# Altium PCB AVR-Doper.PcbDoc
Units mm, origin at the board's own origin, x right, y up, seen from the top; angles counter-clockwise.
Board outline 152.4 x 101.6 mm, 2 copper layers (Top Layer, Bottom Layer); 39 components, 29 nets, 126 pads, 0 vias.
Unrouted connection lines stored in the file: 5.
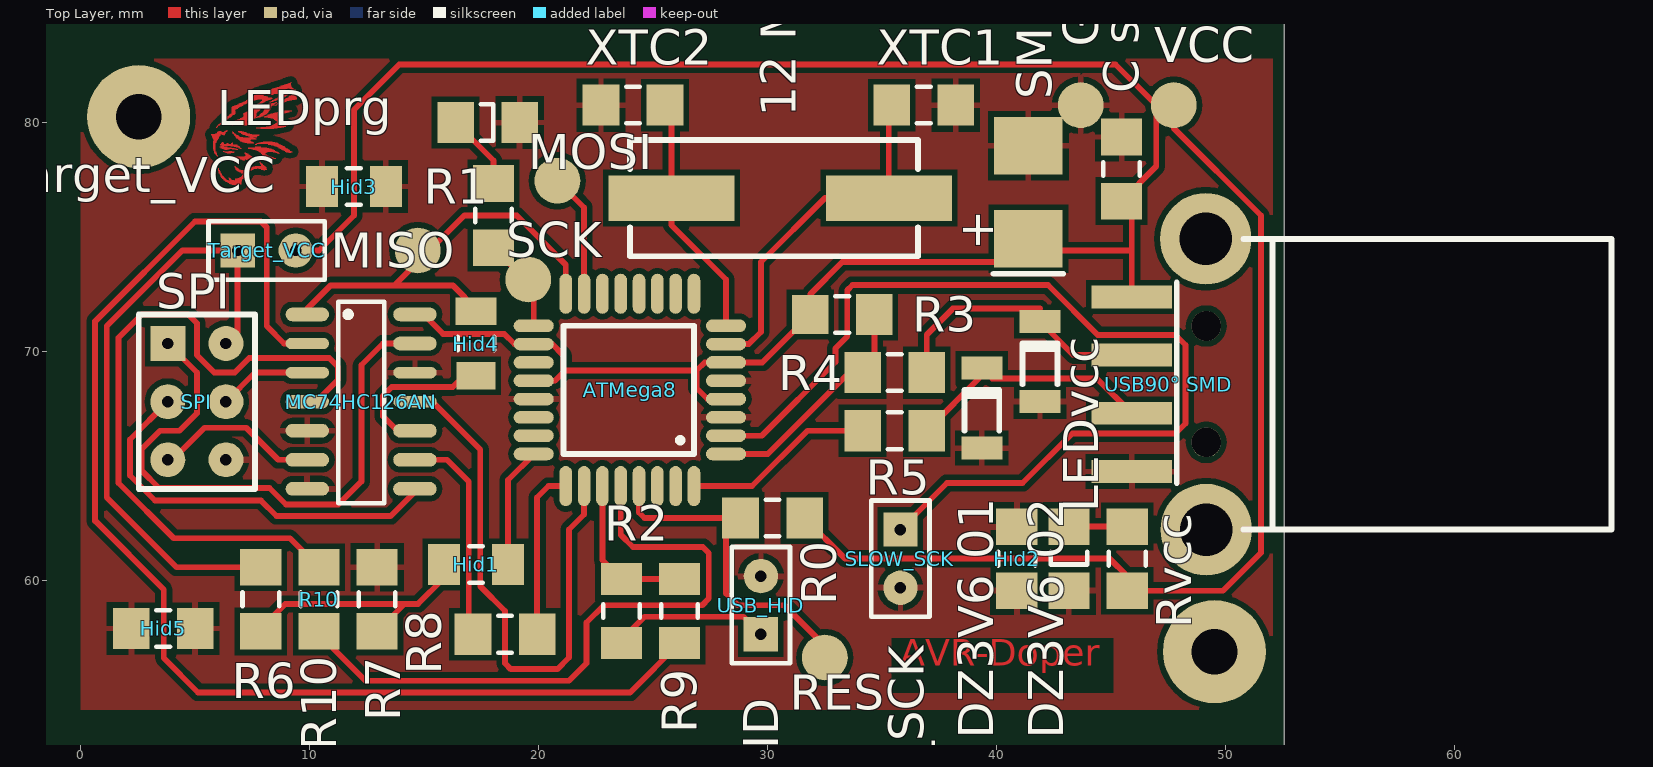
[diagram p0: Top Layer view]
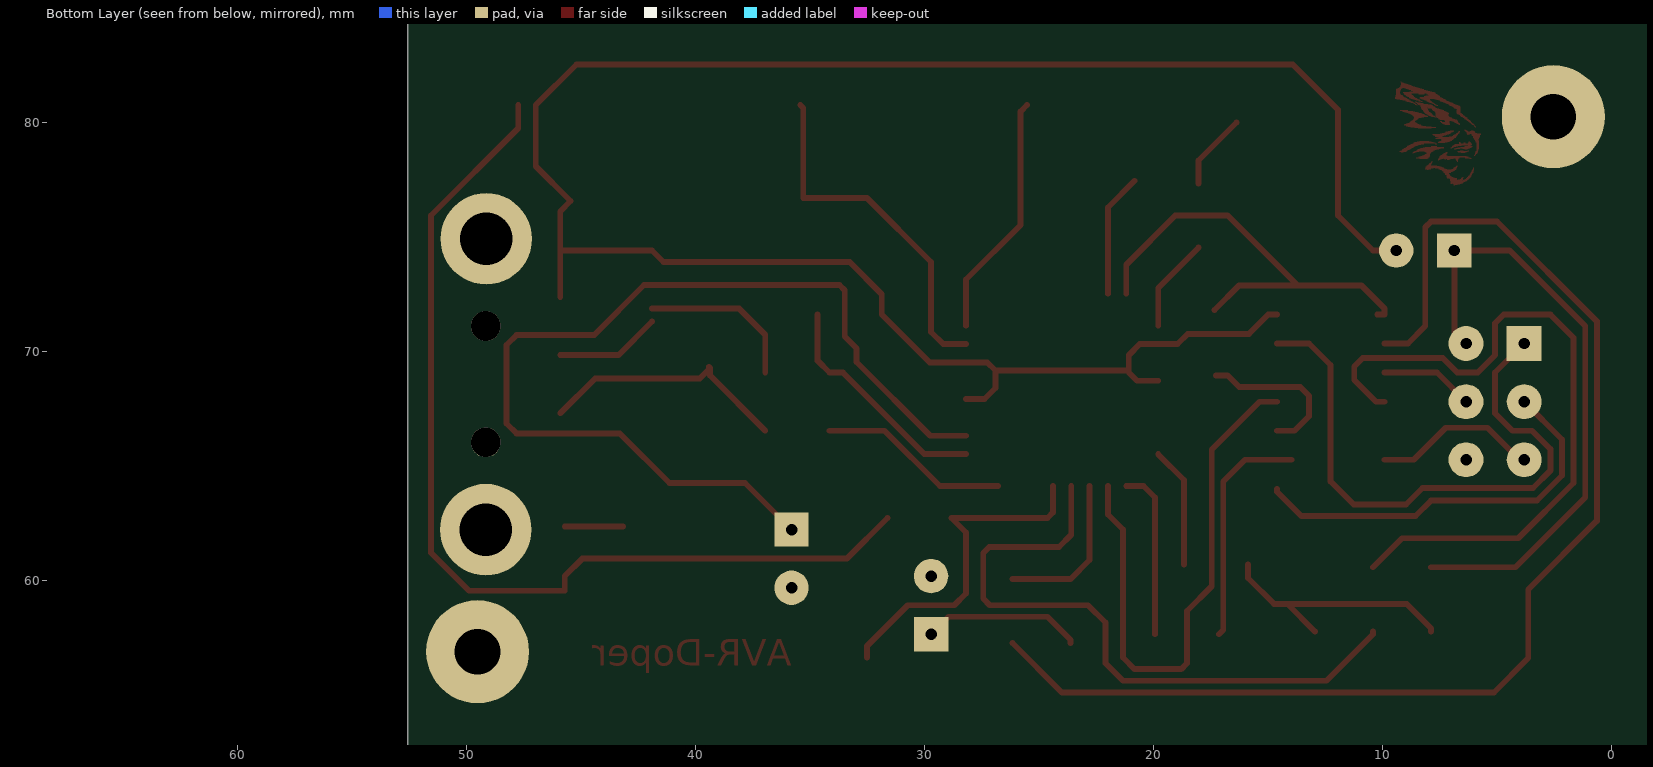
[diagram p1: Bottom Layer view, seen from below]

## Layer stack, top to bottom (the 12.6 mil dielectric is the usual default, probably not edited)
Top Layer: signal copper 0.0356
Dielectric: dielectric 0.32, FR-4, Dk 4.8
Bottom Layer: signal copper 0.0356

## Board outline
-99.822,25.4 52.578,25.4 52.578,127 -99.822,127

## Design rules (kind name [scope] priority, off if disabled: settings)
Clearance [All] p1: gap=0.254
PolygonConnect [All] p1: connectstyle=Relief reliefconductorwidth=0.254 reliefentries=4 polygonreliefangle="90 Angle"
RoutingVias [All] p1: holewidth=0.711 width=1.27 viastyle="Through Hole" minholewidth=0.711 minwidth=1.27 maxholewidth=0.711 maxwidth=1.27
SilkscreenOverComponentPads [All] p1: minsilkscreentomaskgap=0.254
SolderMaskExpansion [All] p1: expansion=0.102
TestPointUsage [All] p1: valid=0 allowmultiple=FALSE
Testpoint [All] p1: side=15 testpointundercomponent=TRUE minsize=1.016 maxsize=2.54 preferedsize=1.524 minholesize=0 maxholesize=1.016 preferedholesize=0.813 testpointgrid=0.025 style=1023 order=0123456789
Width [All] p1: maxlimit=0.254 minlimit=0.254 preferedwidth=0.254
23 further rules are at their usual default settings.

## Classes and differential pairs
component class AVR-Doper: "12 MHZ" ATMega8 "ATmega88 SMD" "C sz1" "DZ3V6 01" "DZ3V6 02" GND LEDprg LEDvcc MC74HC126AN MISO MOSI R0 R1 R2 R3 R4 R5 R6 R7 R8 R9 R10 RES Rvcc SCK SLOW_SCK "SMD 47uF" SPI Target_VCC "USB90° SMD" USB_HID VCC XTC1 XTC2

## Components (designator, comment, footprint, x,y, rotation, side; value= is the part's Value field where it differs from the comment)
"12 MHZ" "12 MHZ" Quartz 35.306,76.708 r180 top (schematic designator "? MHZ")
ATMega8 "ATMega8" ATMega8 28.194,65.532 r180 top
"C sz1" "Cap" "SM 3216[1206]"#1 45.466,77.978 r90 top
"DZ3V6 01" "Diode" DO-80 39.37,65.786 r90 top
"DZ3V6 02" "Diode" DO-80 41.91,67.818 r90 top
GND "Mérőpont" Mérőpont 43.688,80.772 r0 top
Hid1 "Res" "SM 3216[1206]"#2 17.272,60.706 r180 top (schematic designator RRES)
Hid2 "Res" "SM 3216[1206]"#1 40.894,60.96 r270 top (schematic designator RRES)
Hid3 "Res" "SM 3216[1206]"#2 11.938,77.216 r0 top (schematic designator RRES)
Hid4 "Res" "SM 3216[1206]"#3 17.272,70.358 r90 top (schematic designator RRES)
Hid5 "Res" "SM 3216[1206]"#1 3.607,57.912 r0 top (schematic designator RRES)
LEDprg "LED" "SM 3216[1206] - pol" 17.78,80.01 r0 top
LEDvcc "LED" "SM 3216[1206] - pol" 43.18,60.96 r270 top
MC74HC126AN "SMD 14 láb" "SMD 14 láb" 9.906,71.628 r0 top
MISO "Mérőpont" Mérőpont 14.732,74.422 r90 top
MOSI "Mérőpont" Mérőpont 20.828,77.47 r90 top
R0 "Res" "SM 3216[1206]"#1 30.226,62.738 r0 top
R1 "Res" "SM 3216[1206]"#1 18.034,75.946 r270 top
R2 "Res" "SM 3216[1206]"#2 23.622,58.674 r90 top
R3 "Res" "SM 3216[1206]"#4 33.274,71.628 r0 top
R4 "Res" "SM 3216[1206]"#1 35.56,69.088 r180 top
R5 "Res" "SM 3216[1206]"#1 35.56,66.548 r180 top
R6 "Res" "SM 3216[1206]"#1 7.874,59.182 r270 top
R7 "Res" "SM 3216[1206]"#1 12.954,59.182 r90 top
R8 "Res" "SM 3216[1206]"#1 18.542,57.658 r0 top
R9 "Res" "SM 3216[1206]"#2 26.162,58.674 r270 top
R10 "Res" "SM 3216[1206]"#1 10.414,59.182 r90 top
RES "Mérőpont" Mérőpont 32.512,56.642 r0 top
Rvcc "Res" "SM 3216[1206]"#1 45.72,60.96 r270 top
SCK "Mérőpont" Mérőpont 19.558,73.152 r0 top
SLOW_SCK "Header 2" HDR1X2 35.814,62.23 r270 top
"SMD 47uF" "SMD 47uF" "SMD 47uF" 41.402,74.93 r90 top
SPI "SPI" SPI 3.81,70.358 r0 top
Target_VCC "Header 2" HDR1X2 6.858,74.422 r0 top
"USB90° SMD" "USB90° SMD" "USB90° SMD" 52.07,74.93 r270 top
USB_HID "Header 2" HDR1X2 29.718,57.658 r90 top
VCC "Mérőpont" Mérőpont 47.752,80.772 r0 top
XTC1 "Cap" "SM 3216[1206]"#1 36.83,80.772 r0 top
XTC2 "Cap" "SM 3216[1206]"#1 24.13,80.772 r180 top

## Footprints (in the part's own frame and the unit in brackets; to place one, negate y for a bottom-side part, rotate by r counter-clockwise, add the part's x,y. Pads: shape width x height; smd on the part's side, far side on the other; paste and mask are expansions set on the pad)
ATMega8 [mm]
  oval 1.75x0.55 smd: 1(0,0) 2(0,-0.8) 3(0,-1.6) 4(0,-2.4) 5(0,-3.2) 6(0,-4) 7(0,-4.8) 8(0,-5.6) 17(8.4,-5.6) 18(8.4,-4.8) 19(8.4,-4) 20(8.4,-3.2) 21(8.4,-2.4) 22(8.4,-1.6) 23(8.4,-0.8) 24(8.4,0)
  oval 0.55x1.75 smd: 9(1.4,-7) 10(2.2,-7) 11(3,-7) 12(3.8,-7) 13(4.6,-7) 14(5.4,-7) 15(6.2,-7) 16(7,-7) 25(7,1.4) 26(6.2,1.4) 27(5.4,1.4) 28(4.6,1.4) 29(3.8,1.4) 30(3,1.4) 31(2.2,1.4) 32(1.4,1.4)
  silkscreen extent 1.4,-5.6 7.1,0
DO-80 [mm]
  rect 1x1.8 smd: 1(0,0) 2(3.5,0)
  silkscreen extent 0.76,-0.76 2.54,0.76
HDR1X2 [mm] "Connector; Header; 2 Position"
  rect 1.5x1.5 hole 0.5: 1(0,0)
  round 1.5 hole 0.5: 2(2.54,0)
  silkscreen extent -1.27,-1.27 3.81,1.27
Mérőpont [mm]
  round 2 smd: 1(0,0)
Quartz [mm]
  rect 5.5x2 smd: 1(0,0) 2(9.5,0)
  silkscreen extent -1.27,-2.54 11.3,2.54
"SM 3216[1206]"#1 [mm] "Chip Resistor; Body 3.2 x 1.6 mm (LxW typ)"
  rect 1.6x1.8 smd: 1(-1.4,0) 2(1.4,0)
  silkscreen extent -0.3,-0.8 0.3,0.8
"SM 3216[1206]"#2 [mm] "Chip Resistor; Body 3.2 x 1.6 mm (LxW typ)"
  rect 1.4x1.8 smd: 1(-1.4,0) 2(1.4,0)
  silkscreen extent -0.3,-0.8 0.3,0.8
"SM 3216[1206]"#3 [mm] "Chip Resistor; Body 3.2 x 1.6 mm (LxW typ)"
  rect 1.2x1.7 smd: 1(-1.4,0)
  rect 1.2x1.8 smd: 2(1.4,0)
  silkscreen extent -0.3,-0.8 0.3,0.8
"SM 3216[1206]"#4 [mm] "Chip Resistor; Body 3.2 x 1.6 mm (LxW typ)"
  rect 1.6x1.7 smd: 1(-1.4,0)
  rect 1.6x1.8 smd: 2(1.4,0)
  silkscreen extent -0.3,-0.8 0.3,0.8
"SM 3216[1206] - pol" [mm] "Polarized Chip; Body 3.2 x 1.6 mm (LxW typ)"
  rect 1.6x1.8 smd: 1(-1.4,0) 2(1.4,0)
  silkscreen extent -0.3,-0.8 0.25,0.8
"SMD 14 láb" [mm]
  oval 1.9x0.6 smd: 1(0,0) 4(0,-3.81) 5(0,-5.08) 6(0,-6.35) 7(0,-7.62) 8(4.699,-7.62) 9(4.7,-6.35) 10(4.7,-5.08) 13(4.7,-1.27) 14(4.7,0)
  oval 1.9x0.5 smd: 2(0,-1.27) 3(0,-2.54) 11(4.7,-3.81) 12(4.7,-2.54)
  silkscreen extent 1.35,-8.25 3.35,0.55
"SMD 47uF" [mm]
  rect 2.5x3 smd: 1(0,0) 2(4.064,0)
  silkscreen extent -1.52,-1.52 -1.52,1.52
SPI [mil]
  rect 60x60 hole 19.68: 1(0,0)
  round 60 hole 19.68: 2(100,0) 3(0,-100) 4(100,-100) 5(0,-200) 6(100,-200)
  silkscreen extent -50,-250 150,50
"USB90° SMD" [mm]
  round 4 hole 2.3: 0(0,-2.921) 0(12.7,-2.9)
  round 1.3 hole 1.3: 0(3.81,-2.9) 0(8.89,-2.9)
  rect 1x3.5 smd: 1(2.54,-6.155) 2(5.08,-6.155) 3(7.62,-6.155) 4(10.16,-6.155)
  silkscreen extent 0,-4.19 12.7,14.8

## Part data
"12 MHZ": library part Quartz, "SMD"
"C sz1" XTC1 XTC2: "Capacitor"
Hid1 Hid2 Hid3 Hid4 Hid5 R0 R1 R2 R3 R4 R5 R6 R7 R8 R9 R10 Rvcc: "Resistor"
SLOW_SCK Target_VCC USB_HID: "Header, 2-Pin"

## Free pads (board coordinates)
  round 4.5 hole 2: 0(2.54,80.264) 0(49.53,56.896)

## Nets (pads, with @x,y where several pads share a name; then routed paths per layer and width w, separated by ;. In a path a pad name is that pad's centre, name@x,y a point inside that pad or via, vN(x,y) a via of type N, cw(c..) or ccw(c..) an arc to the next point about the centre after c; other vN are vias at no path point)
+5: "C sz1.1" "SMD 47uF.1" "USB90° SMD.1" ATMega8.4 ATMega8.6 ATMega8.18 ATMega8.20 MC74HC126AN.14 R0.2 R3.1 Rvcc.2 Target_VCC.2 VCC.1 | length 136.1
  Top Layer w0.254: Target_VCC.2 10.414,74.422 11.938,75.946 11.938,80.569 13.919,82.55 45.212,82.55 46.99,80.772 46.99,78.102 45.466,76.578 45.915,76.129 45.915,74.422 ; MC74HC126AN.14 14.986,71.628 15.837,70.777 18.504,70.777 18.949,70.332 ATMega8.18 20.6,70.332 21.082,69.85 21.082,69.088 20.726,68.732 ATMega8.20 ; 21.17,69.176 26.906,69.176 ; ATMega8.4 27.388,67.932 26.906,68.414 26.906,69.176 ; R0.2 33.404,60.96 44.958,60.96 45.72,60.198 Rvcc.2 49.908,59.56 51.562,61.214 51.562,75.946 47.752,79.756 VCC.1 ; 45.915,72.39 45.915,74.422 ; 26.906,69.176 27.262,69.532 ATMega8.6 29.778,69.532 R3.1 31.874,72.514 33.274,73.914 41.402,73.914 41.91,74.422 45.915,74.422
GND: "C sz1.2" "DZ3V6 01.1" "DZ3V6 02.1" "SMD 47uF.2" "USB90° SMD.4" ATMega8.3 ATMega8.5 ATMega8.21 GND.1 Hid2.1 Hid2.2 Hid3.1 Hid3.2 Hid5.1 Hid5.2 LEDprg.2 LEDvcc.2 MC74HC126AN.5 MC74HC126AN.7 MC74HC126AN.12 R7.2 SLOW_SCK.2 SPI.6 USB_HID.2 XTC1.2 XTC2.2
"LED PRG": ATMega8.17 R1.2 SCK.1 | length 4.1
  Top Layer w0.254: R1.2 19.794,72.786 ATMega8.17
MISO: MC74HC126AN.13 SPI.1 | length 26
  Top Layer w0.254: SPI.1 5.08,69.088 5.08,67.31 4.318,66.548 3.464,66.548 2.667,65.751 2.667,64.805 3.424,64.048 8.253,64.048 8.974,63.327 11.257,63.327 12.266,64.336 12.266,69.416 13.208,70.358 MC74HC126AN.13
MOSI: MC74HC126AN.3 SPI.4 | length 4.1
  Top Layer w0.254: SPI.4 7.62,69.088 MC74HC126AN.3
"NetDZ3V6 01_2": "DZ3V6 01.2" "USB90° SMD.3" R5.1 | length 11.2
  Top Layer w0.254: R5.1 39.37,68.958 39.37,69.286 ; 39.426,69.342 39.37,69.286 ; 45.915,67.31 44.391,68.834 39.822,68.834 39.37,69.286
"NetDZ3V6 02_2": "DZ3V6 02.2" "USB90° SMD.2" R4.1 | length 11.7
  Top Layer w0.254: R4.1 36.96,70.742 38.1,71.882 41.91,71.882 ; 41.91,71.318 43.378,69.85 45.915,69.85
NetLEDprg_1: LEDprg.1 R1.1 | length 3.3
  Top Layer w0.254: LEDprg.1 18.034,78.356 R1.1
NetLEDvcc_1: LEDvcc.1 Rvcc.1 | length 2.5
  Top Layer w0.254: LEDvcc.1 Rvcc.1
NetMC74HC126AN_2: MC74HC126AN.2 R9.2 | length 55.8
  Top Layer w0.254: MC74HC126AN.2 8.89,70.358 8.128,71.12 8.128,75.438 7.874,75.692 4.997,75.692 0.635,71.33 0.635,62.611 3.632,59.614 3.632,56.617 5.131,55.118 24.006,55.118 R9.2
NetMC74HC126AN_4: MC74HC126AN.4 R10.2 | length 31.2
  Top Layer w0.254: MC74HC126AN.4 10.287,67.818 11.237,68.768 11.237,69.349 10.863,69.723 7.366,69.723 6.731,69.088 5.842,69.088 5.08,69.85 5.08,71.247 4.699,71.628 2.667,71.628 1.651,70.612 1.651,64.262 4.064,61.849 9.147,61.849 R10.2
NetMC74HC126AN_9: MC74HC126AN.9 R8.1 | length 10.1
  Top Layer w0.254: MC74HC126AN.9@13.97,65.278 16.002,65.278 16.953,64.327 16.953,57.847 R8.1
NetR2_1: R2.1 USB_HID.1 | length 7
  Top Layer w0.254: R2.1 23.622,57.404 24.638,58.42 28.956,58.42 USB_HID.1
"OUT EN": ATMega8.16 Hid4.1 Hid4.2 MC74HC126AN.1 MC74HC126AN.10 MISO.1 | length 26.8
  Top Layer w0.254: MC74HC126AN.1@10.228,71.628 MC74HC126AN.1 9.906,71.882 10.922,72.898 13.716,72.898 ; MC74HC126AN.10 13.843,66.548 13.208,67.183 13.208,68.072 13.589,68.453 16.259,68.453 16.764,68.958 Hid4.1 ; Hid4.2@17.334,71.82 16.256,72.898 13.716,72.898 ; ATMega8.16 21.194,73.802 19.05,75.946 16.764,75.946 13.716,72.898
PRGM: ATMega8.15 MOSI.1 | length 5.4
  Top Layer w0.254: MOSI.1 21.994,76.304 ATMega8.15
RES: ATMega8.29 R0.1 RES.1 | length 15
  Top Layer w0.254: ATMega8.29 24.394,62.982 24.638,62.738 R0.1 28.194,62.106 28.194,59.436 28.702,58.928 30.734,58.928 32.512,57.15 RES.1
RESET: MC74HC126AN.6 SPI.5 | length 7.3
  Top Layer w0.254: SPI.5 4.015,65.278 5.412,66.675 7.239,66.675 8.636,65.278 MC74HC126AN.6
SCK: MC74HC126AN.8 SPI.3 | length 17.7
  Top Layer w0.254: SPI.3 2.159,66.167 2.159,64.594 3.253,63.5 7.874,63.5 8.555,62.819 13.543,62.819 14.605,63.881 MC74HC126AN.8
"SLOW SCK": ATMega8.2 SLOW_SCK.1 | length 43.2
  Top Layer w0.254: ATMega8.2 29.756,66.332 32.979,69.555 32.979,70.146 33.493,70.66 33.493,72.686 33.716,72.909 42.258,72.909 44.436,70.731 47.823,70.731 48.26,70.294 48.26,66.866 47.823,66.429 43.315,66.429 41.148,64.262 37.846,64.262 SLOW_SCK.1
TMISO: ATMega8.26 MC74HC126AN.11 | length 24.4
  Top Layer w0.254: MC74HC126AN.11 15.367,67.818 17.461,65.724 17.461,59.755 18.542,58.674 18.542,56.388 18.796,56.134 20.828,56.134 21.336,56.642 21.336,62.23 21.994,62.888 ATMega8.26
TMOSI: ATMega8.27 R2.2 R9.1 | length 6.9
  Top Layer w0.254: ATMega8.27 22.794,60.902 R2.2 R9.1
TRESET: ATMega8.28 R10.1 | length 28.8
  Top Layer w0.254: R10.1 10.414,57.658 12.446,55.626 21.336,55.626 22.098,56.388 22.098,58.166 22.86,58.928 27.155,58.928 27.443,59.216 27.443,61.203 27.178,61.468 24.13,61.468 23.594,62.004 ATMega8.28
TSCK: ATMega8.25 R8.2 | length 7.4
  Top Layer w0.254: R8.2 19.942,63.63 20.444,64.132 ATMega8.25
"USB D+": ATMega8.32 R5.2 | length 8.4
  Top Layer w0.254: ATMega8.32 29.334,64.132 31.75,66.548 R5.2
"USB D-": ATMega8.1 R3.2 R4.2 | length 10.2
  Top Layer w0.254: ATMega8.1 30.016,65.532 33.572,69.088 R4.2 34.674,69.602 R3.2
VCCINT: ATMega8.24 Hid1.1 Hid1.2 R6.2 R7.1 | length 16.6
  Top Layer w0.254: R6.2 7.874,57.912 8.941,58.979 14.151,58.979 ; R7.1 14.151,58.979 ; Hid1.2 15.872,60.119 14.732,58.979 14.151,58.979 ; Hid1.1 18.672,64.392 19.794,65.514 ATMega8.24
VTARGET: R6.1 SPI.2 Target_VCC.1 | length 26.8
  Top Layer w0.254: SPI.2 6.858,70.866 Target_VCC.1 4.445,74.422 1.143,71.12 1.143,63.627 4.188,60.582 R6.1
XT1: "12 MHZ.1" ATMega8.7 XTC1.1 | length 15.7
  Top Layer w0.254: ATMega8.7 29.184,70.332 29.718,70.866 29.718,73.914 32.512,76.708 35.306,76.708 35.306,80.648 XTC1.1
XT2: "12 MHZ.2" ATMega8.8 XTC2.1 | length 10.7
  Top Layer w0.254: XTC2.1 25.806,80.496 25.806,76.708 25.806,75.54 28.194,73.152 ATMega8.8
pads on no net: "USB90° SMD.0" ATMega8.9 ATMega8.10 ATMega8.11 ATMega8.12 ATMega8.13 ATMega8.14 ATMega8.19 ATMega8.22 ATMega8.23 ATMega8.30 ATMega8.31
copper on no net: | length 133.8
  Top Layer w0.025: 5.715,79.477 6.096,79.477 ; 5.715,79.502 6.096,79.502 ; 5.74,79.4 6.045,79.4 ; 5.74,79.426 6.071,79.426 ; 5.74,79.451 6.096,79.451 ; 5.766,79.35 6.045,79.35 ; 5.766,79.375 6.045,79.375 ; 5.791,78.867 5.893,78.867 ; 5.791,78.892 5.893,78.892 ; 5.791,78.918 5.893,78.918 ; 5.791,78.943 5.893,78.943 ; 5.791,78.969 5.893,78.969 ; 5.791,78.994 5.893,78.994 ; 5.791,79.019 5.893,79.019 ; 5.791,79.045 5.893,79.045 ; 5.791,79.07 5.893,79.07 ; 5.791,79.096 5.893,79.096 ; 5.791,79.121 5.893,79.121 ; 5.791,79.146 5.918,79.146 ; 5.791,79.172 5.918,79.172 ; 5.791,79.197 5.918,79.197 ; 5.791,79.299 5.994,79.299 ; 5.791,79.324 6.02,79.324 ; 5.817,78.791 5.893,78.791 ; 5.817,78.816 5.893,78.816 ; 5.817,78.842 5.893,78.842 ; 5.817,79.223 5.944,79.223 ; 5.817,79.248 5.969,79.248 ; 5.817,79.273 5.994,79.273 ; 5.842,78.715 5.918,78.715 ; 5.842,78.74 5.918,78.74 ; 5.842,78.765 5.893,78.765 ; 5.867,78.664 5.944,78.664 ; 5.867,78.689 5.918,78.689 ; 5.893,78.638 5.944,78.638 ; 5.893,79.527 6.299,79.527 ; 5.918,78.613 5.944,78.613 ; 5.918,79.807 5.944,79.807 ; 5.944,78.588 5.969,78.588 ; 5.944,79.553 6.325,79.553 ; 5.944,79.832 5.969,79.832 ; 5.969,78.562 5.994,78.562 ; 5.969,79.578 6.325,79.578 ; 5.969,79.858 5.994,79.858 ; 5.994,79.604 6.172,79.604 ; 5.994,79.883 6.02,79.883 ; 6.02,77.927 6.071,77.927 ; 6.02,77.953 6.045,77.953 ; 6.02,77.978 6.045,77.978 ; 6.02,78.003 6.045,78.003 ; 6.02,79.908 6.071,79.908 ; 6.045,77.826 6.121,77.826 ; 6.045,77.851 6.096,77.851 ; 6.045,77.876 6.096,77.876 ; 6.045,77.902 6.071,77.902 ; 6.045,79.629 6.121,79.629 ; 6.045,79.934 6.096,79.934 ; 6.071,77.775 6.147,77.775 ; 6.071,77.8 6.147,77.8 ; 6.071,78.943 6.274,78.943 ; 6.071,79.959 6.121,79.959 ; 6.096,77.724 6.172,77.724 ; 6.096,77.749 6.172,77.749 ; 6.096,79.045 6.833,79.045 ; 6.096,79.07 6.655,79.07 ; 6.096,79.985 6.147,79.985 ; 6.121,77.673 6.223,77.673 ; 6.121,77.699 6.198,77.699 ; 6.121,78.435 6.198,78.435 ; 6.121,78.918 6.579,78.918 ; 6.121,78.969 6.248,78.969 ; 6.121,80.01 6.198,80.01 ; 6.147,77.622 6.248,77.622 ; 6.147,77.648 6.248,77.648 ; 6.147,79.096 6.248,79.096 ; 6.147,80.035 6.223,80.035 ; 6.172,78.461 6.375,78.461 ; 6.172,79.019 6.833,79.019 ; 6.172,79.121 6.223,79.121 ; 6.172,80.061 6.248,80.061 ; 6.198,77.572 6.299,77.572 ; 6.198,77.597 6.299,77.597 ; 6.198,78.892 6.706,78.892 ; 6.198,79.146 6.223,79.146 ; 6.198,79.502 6.299,79.502 ; 6.198,80.086 6.299,80.086 ; 6.223,77.546 6.35,77.546 ; 6.223,78.765 6.274,78.765 ; 6.223,80.112 6.325,80.112 ; 6.248,77.521 6.375,77.521 ; 6.248,78.486 7.493,78.486 ; 6.248,78.867 6.502,78.867 ; 6.248,79.477 6.274,79.477 ; 6.248,80.137 6.35,80.137 ; 6.274,79.604 6.35,79.604 ; 6.299,77.495 6.452,77.495 ; 6.299,78.74 6.706,78.74 ; 6.299,78.842 6.401,78.842 ; 6.299,78.943 6.401,78.943 ; 6.299,79.629 6.375,79.629 ; 6.299,80.162 6.401,80.162 ; 6.299,80.188 6.426,80.188 ; 6.325,77.47 6.502,77.47 ; 6.35,77.445 7.01,77.445 ; 6.35,78.511 7.493,78.511 ; 6.35,78.715 6.68,78.715 ; 6.35,79.654 6.401,79.654 ; 6.35,80.213 6.477,80.213 ; 6.375,79.096 6.452,79.096 ; 6.375,79.68 6.401,79.68 ; 6.375,80.239 6.502,80.239 ; 6.401,77.419 6.985,77.419 ; 6.401,78.689 6.553,78.689 ; 6.401,80.264 6.553,80.264 ; 6.426,80.289 6.579,80.289 ; 6.452,77.394 7.01,77.394 ; 6.477,77.597 6.502,77.597 ; 6.477,78.765 6.604,78.765 ; 6.477,80.315 6.604,80.315 ; 6.502,77.368 7.01,77.368 ; 6.502,77.521 6.604,77.521 ; 6.502,77.546 6.553,77.546 ; 6.502,77.572 6.528,77.572 ; 6.502,80.34 6.655,80.34 ; 6.528,77.495 6.706,77.495 ; 6.528,80.366 6.706,80.366 ; 6.553,77.343 6.909,77.343 ; 6.553,77.47 7.036,77.47 ; 6.553,78.994 6.883,78.994 ; 6.553,80.391 6.731,80.391 ; 6.579,79.096 6.655,79.096 ; 6.604,80.416 6.756,80.416 ; 6.604,80.442 6.756,80.442 ; 6.604,80.467 6.756,80.467 ; 6.604,80.493 6.756,80.493 ; 6.604,80.518 6.756,80.518 ; 6.604,80.543 6.731,80.543 ; 6.604,80.569 6.731,80.569 ; 6.604,80.594 6.756,80.594 ; 6.604,80.62 6.807,80.62 ; 6.604,80.645 6.858,80.645 ; 6.604,80.67 6.909,80.67 ; 6.629,77.318 6.883,77.318 ; 6.629,78.867 6.807,78.867 ; 6.629,79.121 6.655,79.121 ; 6.629,79.604 6.655,79.604 ; 6.629,79.908 6.655,79.908 ; 6.629,79.934 6.68,79.934 ; 6.629,80.696 6.934,80.696 ; 6.655,78.461 7.518,78.461 ; 6.655,79.553 6.706,79.553 ; 6.655,79.578 6.68,79.578 ; 6.655,79.959 6.731,79.959 ; 6.655,80.721 6.985,80.721 ; 6.68,78.41 6.807,78.41 ; 6.68,78.435 6.807,78.435 ; 6.68,79.527 6.756,79.527 ; 6.68,79.985 6.782,79.985 ; 6.68,80.01 6.833,80.01 ; 6.706,78.308 6.731,78.308 ; 6.706,78.334 6.756,78.334 ; 6.706,78.359 6.782,78.359 ; 6.706,78.384 6.782,78.384 ; 6.706,78.969 6.934,78.969 ; 6.706,79.477 6.807,79.477 ; 6.706,79.502 6.782,79.502 ; 6.706,80.035 6.883,80.035 ; 6.706,80.747 7.036,80.747 ; 6.731,77.292 6.883,77.292 ; 6.731,78.08 6.782,78.08 ; 6.731,78.105 6.756,78.105 ; 6.731,79.451 6.858,79.451 ; 6.731,80.061 6.985,80.061 ; 6.731,80.086 7.29,80.086 ; 6.756,77.521 7.036,77.521 ; 6.756,77.546 7.061,77.546 ; 6.756,78.029 6.833,78.029 ; 6.756,78.054 6.807,78.054 ; 6.756,79.426 6.909,79.426 ; 6.756,80.112 7.29,80.112 ; 6.782,77.495 7.036,77.495 ; 6.782,77.978 6.909,77.978 ; 6.782,78.003 6.883,78.003 ; 6.782,78.842 6.858,78.842 ; 6.782,79.4 6.96,79.4 ; 6.782,80.772 7.087,80.772 ; 6.807,77.953 6.985,77.953 ; 6.807,78.943 6.96,78.943 ; 6.807,79.35 7.544,79.35 ; 6.807,79.375 7.087,79.375 ; 6.833,77.267 6.883,77.267 ; 6.833,77.927 7.417,77.927 ; 6.833,80.137 7.468,80.137 ; 6.833,80.797 7.112,80.797 ; 6.858,77.572 7.163,77.572 ; 6.858,77.902 7.391,77.902 ; 6.858,79.324 7.62,79.324 ; 6.883,79.299 7.671,79.299 ; 6.883,79.629 7.036,79.629 ; 6.909,77.876 7.366,77.876 ; 6.909,78.435 7.315,78.435 ; 6.909,78.918 6.985,78.918 ; 6.909,79.273 7.442,79.273 ; 6.909,79.604 7.137,79.604 ; 6.909,80.162 7.544,80.162 ; 6.909,80.823 7.188,80.823 ; 6.934,77.597 7.137,77.597 ; 6.934,79.248 7.417,79.248 ; 6.96,77.343 7.01,77.343 ; 6.96,77.851 7.315,77.851 ; 6.96,79.578 7.239,79.578 ; 6.96,80.848 7.239,80.848 ; 6.985,77.622 7.188,77.622 ; 6.985,78.892 7.01,78.892 ; 6.985,79.223 7.417,79.223 ; 6.985,80.188 7.569,80.188 ; 7.01,77.648 7.188,77.648 ; 7.01,77.826 7.315,77.826 ; 7.01,79.553 7.29,79.553 ; 7.036,77.673 7.188,77.673 ; 7.036,78.41 7.137,78.41 ; 7.036,79.197 7.442,79.197 ; 7.036,80.213 7.62,80.213 ; 7.036,80.874 7.29,80.874 ; 7.061,77.699 7.188,77.699 ; 7.061,79.527 7.391,79.527 ; 7.061,79.908 7.264,79.908 ; 7.061,79.934 7.315,79.934 ; 7.087,77.724 7.264,77.724 ; 7.087,78.384 7.163,78.384 ; 7.087,79.172 7.493,79.172 ; 7.087,79.959 7.366,79.959 ; 7.087,79.985 7.391,79.985 ; 7.087,80.01 7.442,80.01 ; 7.087,80.035 7.264,80.035 ; 7.087,80.061 7.264,80.061 ; 7.087,80.239 7.62,80.239 ; 7.087,80.899 7.341,80.899 ; 7.112,77.749 7.264,77.749 ; 7.112,77.775 7.264,77.775 ; 7.112,77.8 7.29,77.8 ; 7.112,79.502 7.468,79.502 ; 7.112,80.264 7.645,80.264 ; 7.112,80.391 7.468,80.391 ; 7.137,80.289 7.645,80.289 ; 7.137,80.315 7.671,80.315 ; 7.137,80.34 7.671,80.34 ; 7.137,80.366 7.671,80.366 ; 7.137,80.416 7.442,80.416 ; 7.137,80.924 7.417,80.924 ; 7.163,78.537 7.468,78.537 ; 7.163,78.664 7.264,78.664 ; 7.163,78.689 7.214,78.689 ; 7.163,79.146 7.544,79.146 ; 7.163,80.442 7.671,80.442 ; 7.188,77.953 7.468,77.953 ; 7.188,78.638 7.315,78.638 ; 7.188,79.477 7.798,79.477 ; 7.188,80.95 7.468,80.95 ; 7.214,78.562 7.442,78.562 ; 7.214,78.588 7.391,78.588 ; 7.214,78.613 7.366,78.613 ; 7.214,80.467 7.696,80.467 ; 7.239,78.41 7.29,78.41 ; 7.239,79.451 7.772,79.451 ; 7.239,80.975 7.544,80.975 ; 7.264,77.978 7.544,77.978 ; 7.264,80.493 7.722,80.493 ; 7.29,79.121 7.569,79.121 ; 7.29,81.001 7.62,81.001 ; 7.315,78.003 7.696,78.003 ; 7.315,78.892 8.23,78.892 ; 7.315,78.918 8.128,78.918 ; 7.315,79.426 7.722,79.426 ; 7.315,80.518 7.772,80.518 ; 7.341,81.026 7.722,81.026 ; 7.366,78.435 7.544,78.435 ; 7.366,81.051 7.849,81.051 ; 7.391,78.029 8.103,78.029 ; 7.391,79.4 7.696,79.4 ; 7.391,80.543 7.798,80.543 ; 7.417,80.035 7.468,80.035 ; 7.417,81.077 8.382,81.077 ; 7.442,78.054 8.103,78.054 ; 7.442,78.41 7.544,78.41 ; 7.468,78.867 8.331,78.867 ; 7.468,80.569 7.823,80.569 ; 7.468,81.102 8.357,81.102 ; 7.493,78.384 7.569,78.384 ; 7.493,80.391 7.671,80.391 ; 7.493,80.416 7.671,80.416 ; 7.493,81.128 8.179,81.128 ; 7.518,78.08 8.077,78.08 ; 7.518,81.153 8.103,81.153 ; 7.544,78.359 7.569,78.359 ; 7.544,78.842 8.382,78.842 ; 7.544,80.594 7.823,80.594 ; 7.569,81.178 7.976,81.178 ; 7.595,80.747 7.62,80.747 ; 7.595,81.204 7.874,81.204 ; 7.62,78.105 7.925,78.105 ; 7.62,78.943 7.874,78.943 ; 7.62,79.07 7.696,79.07 ; 7.62,80.62 7.849,80.62 ; 7.62,81.229 8.001,81.229 ; 7.645,78.816 8.433,78.816 ; 7.645,80.772 7.696,80.772 ; 7.671,79.781 8.585,79.781 ; 7.671,80.239 7.722,80.239 ; 7.671,80.645 8.026,80.645 ; 7.671,81.255 8.077,81.255 ; 7.696,79.096 8.636,79.096 ; 7.696,80.797 7.747,80.797 ; 7.696,81.28 9.068,81.28 ; 7.722,78.791 8.484,78.791 ; 7.722,80.264 7.849,80.264 ; 7.722,80.67 8.306,80.67 ; 7.747,80.289 7.899,80.289 ; 7.747,80.823 7.798,80.823 ; 7.747,81.305 9.093,81.305 ; 7.772,78.003 8.103,78.003 ; 7.772,78.765 8.534,78.765 ; 7.772,79.121 8.585,79.121 ; 7.772,80.696 8.331,80.696 ; 7.772,80.848 7.849,80.848 ; 7.798,80.315 7.976,80.315 ; 7.798,80.721 8.331,80.721 ; 7.823,78.283 7.849,78.283 ; 7.823,78.308 7.849,78.308 ; 7.823,78.74 8.153,78.74 ; 7.823,80.34 8.026,80.34 ; 7.823,80.747 8.331,80.747 ; 7.823,80.874 7.925,80.874 ; 7.849,78.232 7.899,78.232 ; 7.849,78.257 7.874,78.257 ; 7.849,80.366 8.077,80.366 ; 7.849,80.899 7.976,80.899 ; 7.849,81.331 8.814,81.331 ; 7.874,78.181 7.95,78.181 ; 7.874,78.207 7.925,78.207 ; 7.874,78.715 8.103,78.715 ; 7.874,79.146 8.484,79.146 ; 7.874,79.756 8.433,79.756 ; 7.874,79.807 8.763,79.807 ; 7.874,80.391 8.103,80.391 ; 7.874,80.772 8.382,80.772 ; 7.874,80.924 8.026,80.924 ; 7.874,81.051 8.331,81.051 ; 7.899,77.978 8.128,77.978 ; 7.899,78.156 8.001,78.156 ; 7.899,78.664 8.077,78.664 ; 7.899,78.689 8.077,78.689 ; 7.899,80.416 8.128,80.416 ; 7.899,80.95 8.077,80.95 ; 7.925,78.13 8.026,78.13 ; 7.925,78.537 8.255,78.537 ; 7.925,78.562 8.204,78.562 ; 7.925,78.588 8.153,78.588 ; 7.925,78.613 8.128,78.613 ; 7.925,78.638 8.077,78.638 ; 7.925,80.442 8.153,80.442 ; 7.925,80.975 8.153,80.975 ; 7.925,81.001 8.204,81.001 ; 7.925,81.026 8.28,81.026 ; 7.925,81.356 8.636,81.356 ; 7.95,78.105 8.077,78.105 ; 7.95,78.486 8.407,78.486 ; 7.95,78.511 8.331,78.511 ; 7.976,79.172 8.382,79.172 ; 7.976,80.467 8.179,80.467 ; 7.976,80.493 8.204,80.493 ; 8.001,77.953 8.052,77.953 ; 8.001,78.461 8.534,78.461 ; 8.001,80.518 8.23,80.518 ; 8.026,80.264 8.636,80.264 ; 8.026,80.543 8.23,80.543 ; 8.026,80.569 8.255,80.569 ; 8.026,80.797 8.433,80.797 ; 8.026,81.382 8.661,81.382 ; 8.052,78.435 8.382,78.435 ; 8.052,80.289 8.636,80.289 ; 8.052,80.594 8.28,80.594 ; 8.052,80.62 8.28,80.62 ; 8.077,80.645 8.306,80.645 ; 8.103,79.832 8.865,79.832 ; 8.103,81.407 8.738,81.407 ; 8.128,80.315 8.687,80.315 ; 8.179,80.34 8.712,80.34 ; 8.179,81.255 8.407,81.255 ; 8.204,79.07 8.687,79.07 ; 8.204,80.239 8.611,80.239 ; 8.204,81.432 8.839,81.432 ; 8.23,80.823 8.484,80.823 ; 8.255,79.858 8.966,79.858 ; 8.255,80.366 8.763,80.366 ; 8.255,80.924 8.306,80.924 ; 8.28,81.458 8.89,81.458 ; 8.306,80.213 8.611,80.213 ; 8.306,80.391 8.814,80.391 ; 8.331,79.045 8.738,79.045 ; 8.331,79.883 9.042,79.883 ; 8.331,80.95 8.407,80.95 ; 8.357,80.848 8.484,80.848 ; 8.382,80.975 8.534,80.975 ; 8.382,81.483 8.966,81.483 ; 8.407,78.74 8.585,78.74 ; 8.407,79.908 9.017,79.908 ; 8.407,80.188 8.611,80.188 ; 8.407,80.416 8.865,80.416 ; 8.433,79.019 8.788,79.019 ; 8.433,81.001 8.585,81.001 ; 8.433,81.509 9.017,81.509 ; 8.458,79.934 8.966,79.934 ; 8.458,80.162 8.636,80.162 ; 8.484,78.994 8.839,78.994 ; 8.484,80.442 8.941,80.442 ; 8.484,80.772 8.509,80.772 ; 8.484,80.874 8.534,80.874 ; 8.484,81.026 8.687,81.026 ; 8.509,79.959 8.89,79.959 ; 8.509,80.137 8.636,80.137 ; 8.509,81.051 8.738,81.051 ; 8.534,78.715 8.636,78.715 ; 8.534,79.985 8.839,79.985 ; 8.534,80.112 8.661,80.112 ; 8.534,80.797 8.56,80.797 ; 8.534,80.899 8.56,80.899 ; 8.534,81.534 9.093,81.534 ; 8.56,78.969 8.89,78.969 ; 8.56,80.01 8.788,80.01 ; 8.56,80.086 8.687,80.086 ; 8.56,80.823 8.611,80.823 ; 8.56,81.077 8.814,81.077 ; 8.585,78.689 8.661,78.689 ; 8.585,80.035 8.763,80.035 ; 8.585,80.061 8.712,80.061 ; 8.585,80.467 9.017,80.467 ; 8.585,81.102 8.839,81.102 ; 8.585,81.559 9.22,81.559 ; 8.611,78.943 8.915,78.943 ; 8.611,80.848 8.661,80.848 ; 8.636,81.128 8.89,81.128 ; 8.661,78.664 8.687,78.664 ; 8.661,78.918 8.966,78.918 ; 8.661,80.874 8.738,80.874 ; 8.661,81.153 8.941,81.153 ; 8.687,80.493 9.119,80.493 ; 8.687,80.899 8.814,80.899 ; 8.687,81.178 8.966,81.178 ; 8.687,81.585 9.195,81.585 ; 8.712,78.892 8.992,78.892 ; 8.712,81.204 8.992,81.204 ; 8.738,80.924 8.915,80.924 ; 8.738,81.229 9.017,81.229 ; 8.738,81.255 9.042,81.255 ; 8.738,81.61 9.195,81.61 ; 8.763,78.867 9.042,78.867 ; 8.763,80.95 8.992,80.95 ; 8.788,78.842 9.068,78.842 ; 8.839,78.816 9.119,78.816 ; 8.839,80.975 9.119,80.975 ; 8.839,81.636 9.169,81.636 ; 8.865,81.001 9.22,81.001 ; 8.89,78.791 9.144,78.791 ; 8.89,80.518 9.22,80.518 ; 8.89,81.661 9.169,81.661 ; 8.915,81.026 9.373,81.026 ; 8.941,78.765 9.195,78.765 ; 8.941,81.051 9.449,81.051 ; 8.966,81.686 9.169,81.686 ; 8.992,78.74 9.246,78.74 ; 8.992,81.077 9.449,81.077 ; 9.042,81.102 9.449,81.102 ; 9.042,81.712 9.169,81.712 ; 9.093,78.715 9.169,78.715 ; 9.093,81.128 9.423,81.128 ; 9.093,81.737 9.169,81.737 ; 9.119,81.153 9.423,81.153 ; 9.119,81.534 9.246,81.534 ; 9.144,81.178 9.423,81.178 ; 9.144,81.509 9.271,81.509 ; 9.169,81.483 9.322,81.483 ; 9.169,81.763 9.195,81.763 ; 9.195,81.204 9.398,81.204 ; 9.195,81.432 9.398,81.432 ; 9.195,81.458 9.373,81.458 ; 9.22,81.229 9.398,81.229 ; 9.22,81.255 9.398,81.255 ; 9.22,81.382 9.398,81.382 ; 9.22,81.407 9.398,81.407 ; 9.246,81.28 9.398,81.28 ; 9.246,81.305 9.398,81.305 ; 9.246,81.331 9.398,81.331 ; 9.246,81.356 9.398,81.356

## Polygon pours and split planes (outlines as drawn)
GND on Top Layer "Bottom Layer-No Net" (solid, pour order 1000): 0,82.804 52.07,82.804 52.07,54.356 0,54.356 0,82.804

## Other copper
Top Layer:
  text "AVR-Doper" at 35.814,55.88 h2

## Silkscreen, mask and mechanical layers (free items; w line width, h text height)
Mechanical 1:
  lines w0.254: 0,54.356 52.07,54.356 52.07,82.804 0,82.804 0,54.356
